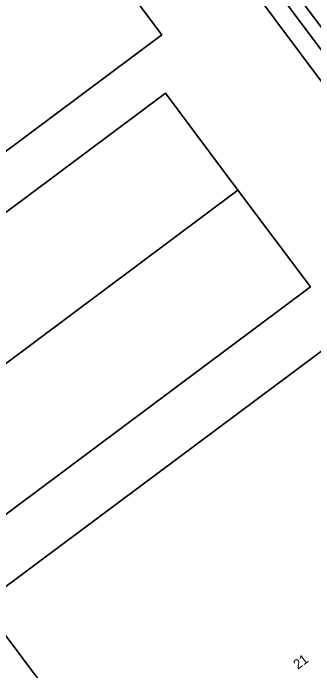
# Model space of a CAD drawing. Extents: x 156702 to 158052, y 387630 to 388992.
# Drawn here: x 157794.6 to 157825.6, y 388524.3 to 388592.3 of the extents above; entities that cross this region are included whole.
import ezdxf

# ---------------------------------------------------------------- set-up
doc = ezdxf.new("R2010")
doc.units = 0
for name, color, linetype in [('IMGEO_Erf', 7, 'Continuous'), ('IMGEO_Oever', 7, 'Continuous'), ('IMGEO_Pand', 7, 'Continuous'), ('IMGEO_Pand_nummerreeks', 7, 'Continuous'), ('IMGEO_Waterloop', 7, 'Continuous')]:
    doc.layers.add(name, color=color, linetype=linetype)

msp = doc.modelspace()

# ---------------------------------------------------------------- linework, layer by layer
at = {"layer": 'IMGEO_Erf'}
msp.add_lwpolyline([(157812.245, 388490.432), (157856.558, 388517.579), (157866.09, 388523.403), (157869.713, 388525.581), (157865.032, 388532.106), (157839.15, 388566.779), (157839.811, 388567.231), (157761.798, 388671.742)], dxfattribs=at)
for points in [[(157795.49, 388609.351), (157800.933, 388602.076), (157809.912, 388590.06), (157770.834, 388560.859), (157767.103, 388565.883), (157766.618, 388565.55), (157767.037, 388564.99), (157762.428, 388561.536), (157758.085, 388567.345), (157758.389, 388567.572), (157758.103, 388567.958), (157757.203, 388567.285), (157755.975, 388568.927), (157756.875, 388569.597), (157756.586, 388569.987), (157756.282, 388569.759), (157751.946, 388575.556), (157756.546, 388578.995), (157756.971, 388578.426), (157757.429, 388578.783), (157756.406, 388580.153)], [(157810.284, 388584.036), (157817.772, 388574.014), (157825.259, 388563.992), (157791.614, 388538.852), (157788.3, 388543.26), (157781.551, 388538.207), (157779.382, 388538.534), (157776.132, 388542.884), (157772.876, 388547.242), (157773.177, 388549.426), (157779.926, 388554.478), (157776.634, 388558.897)], [(157827.776, 388558.382), (157844.257, 388536.356), (157823.506, 388520.914), (157824.174, 388520.021), (157824.869, 388520.528), (157829.311, 388514.601), (157812.889, 388502.304), (157808.45, 388508.262), (157809.15, 388508.808), (157808.513, 388509.637), (157807.828, 388509.101), (157791.323, 388531.165)]]:
    msp.add_lwpolyline(points, close=True, dxfattribs=at)
at = {"layer": 'IMGEO_Oever'}
for points in [[(157752.66, 388690.763), (157751.769, 388690.596), (157750.533, 388689.688), (157749.893, 388688.877), (157749.844, 388688.451), (157749.984, 388688.093), (157751.512, 388686.005), (157757.678, 388677.579), (157761.798, 388671.742), (157839.811, 388567.231), (157865.671, 388532.587), (157870.401, 388525.994), (157870.593, 388526.11), (157870.223, 388526.595), (157870.298, 388527.513), (157872.745, 388529.015), (157874.667, 388530.195), (157874.053, 388532.244), (157871.923, 388533.871), (157794.878, 388635.427), (157770.72, 388667.489), (157765.374, 388674.714)], [(157752.843, 388686.867), (157754.001, 388687.639), (157865.903, 388538.006), (157870.209, 388532.31), (157871.29, 388531.17), (157870.035, 388530.243), (157799.38, 388624.573)]]:
    msp.add_lwpolyline(points, close=True, dxfattribs=at)
at = {"layer": 'IMGEO_Pand'}
for points in [[(157770.834, 388560.859), (157809.912, 388590.06), (157800.933, 388602.076), (157795.49, 388609.351), (157756.406, 388580.153), (157757.429, 388578.783), (157756.971, 388578.426), (157756.546, 388578.995), (157751.946, 388575.556), (157756.282, 388569.759), (157756.586, 388569.987), (157756.875, 388569.597), (157755.975, 388568.927), (157757.203, 388567.285), (157758.103, 388567.958), (157758.389, 388567.572), (157758.085, 388567.345), (157762.428, 388561.536), (157767.037, 388564.99), (157766.618, 388565.55), (157767.103, 388565.883)], [(157817.772, 388574.014), (157810.284, 388584.036), (157776.634, 388558.897), (157779.926, 388554.478), (157773.177, 388549.426), (157772.876, 388547.242), (157776.132, 388542.884)], [(157817.772, 388574.014), (157776.132, 388542.884), (157779.382, 388538.534), (157781.551, 388538.207), (157788.3, 388543.26), (157791.614, 388538.852), (157825.259, 388563.992)], [(157812.889, 388502.304), (157829.311, 388514.601), (157824.869, 388520.528), (157824.174, 388520.021), (157823.506, 388520.914), (157844.257, 388536.356), (157827.776, 388558.382), (157791.323, 388531.165), (157807.828, 388509.101), (157808.513, 388509.637), (157809.15, 388508.808), (157808.45, 388508.262)]]:
    msp.add_lwpolyline(points, close=True, dxfattribs=at)
at = {"layer": 'IMGEO_Waterloop'}
msp.add_lwpolyline([(157870.035, 388530.243), (157871.29, 388531.17), (157870.209, 388532.31), (157865.903, 388538.006), (157754.001, 388687.639), (157752.843, 388686.867), (157799.38, 388624.573)], close=True, dxfattribs=at)

# ---------------------------------------------------------------- texts
at = {"layer": 'IMGEO_Pand_nummerreeks'}
msp.add_text('21', height=1, rotation=36.65503, dxfattribs=at).set_placement((157823.954, 388524.388))

doc.saveas('drawing.dxf')
